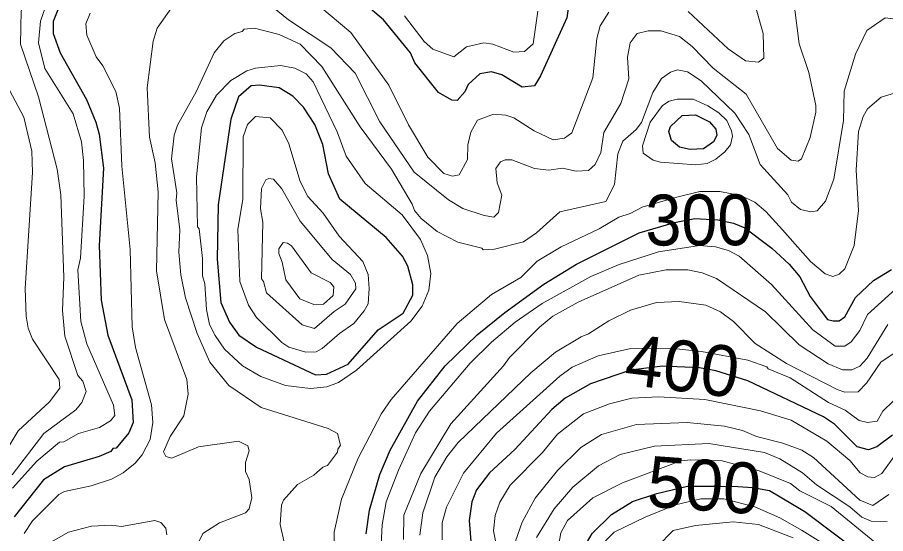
# Model space of a CAD drawing. Extents: x 673.3 to 698.5, y 6984.3 to 7012.3.
# Drawn here: x 677.359 to 678.725, y 6987.614 to 6988.426 of the extents above; entities that cross this region are included whole.
import ezdxf
from ezdxf.enums import TextEntityAlignment as Align

# ---------------------------------------------------------------- set-up
doc = ezdxf.new("R2010")
doc.units = 0
doc.header["$LTSCALE"] = 0.032
doc.layers.add('1', color=7, linetype='Continuous', lineweight=25)
doc.layers.add('2', color=7, linetype='Continuous', lineweight=13)
doc.layers.add('61', color=7, linetype='Continuous')

msp = doc.modelspace()

# ---------------------------------------------------------------- linework, layer by layer
at = {"layer": '1'}
for points in [[(678.2308, 6988.476), (678.2235, 6988.4254), (678.1819, 6988.3339), (678.1726, 6988.3184), (678.153, 6988.3161), (678.1211, 6988.3354), (678.1049, 6988.3403), (678.0865, 6988.337), (678.0683, 6988.3204), (678.063, 6988.3086), (678.0507, 6988.2949), (678.0422, 6988.2958), (678.0216, 6988.3079), (677.9844, 6988.3545), (677.9774, 6988.37), (677.9348, 6988.4223), (677.904, 6988.4481)], [(677.422, 6988.4378), (677.4151, 6988.4193), (677.4149, 6988.4004), (677.4261, 6988.3699), (677.4676, 6988.2967), (677.4823, 6988.2609), (677.4873, 6988.2424), (677.4939, 6988.1885), (677.4872, 6988.0671), (677.4905, 6987.9808)], [(677.9076, 6987.6132), (677.9126, 6987.6506), (677.9293, 6987.7065), (677.9453, 6987.745), (677.9885, 6987.8219), (678.0319, 6987.8776), (678.0824, 6987.9265), (678.1257, 6987.9617), (678.187, 6988.0061), (678.2387, 6988.0378), (678.3371, 6988.087), (678.3927, 6988.1033), (678.4249, 6988.1094), (678.4609, 6988.1073), (678.4857, 6988.1023), (678.5035, 6988.0947), (678.5459, 6988.0628), (678.5734, 6988.0377), (678.5901, 6988.0177), (678.6064, 6987.9868), (678.6222, 6987.9659), (678.6336, 6987.9507), (678.6425, 6987.9484), (678.6521, 6987.9482), (678.6608, 6987.9545), (678.678, 6987.9853), (678.7062, 6988.012), (678.7345, 6988.029)], [(677.4905, 6987.9808), (677.501, 6987.926), (677.5386, 6987.8241), (677.541, 6987.7886), (677.5342, 6987.772), (677.5143, 6987.7478), (677.5088, 6987.7475), (677.5056, 6987.7427), (677.4873, 6987.7349), (677.4326, 6987.7185), (677.3996, 6987.698), (677.3535, 6987.6398)], [(678.7361, 6987.7683), (678.7112, 6987.7501), (678.6981, 6987.7455), (678.6804, 6987.75), (678.6445, 6987.7858), (678.6272, 6987.7974), (678.5083, 6987.854), (678.4578, 6987.8696), (678.432, 6987.8742), (678.374, 6987.8773), (678.3238, 6987.8709), (678.2609, 6987.8493), (678.2208, 6987.8269), (678.1998, 6987.8087), (678.1418, 6987.7457), (678.1019, 6987.709), (678.081, 6987.6824), (678.0738, 6987.6635), (678.0696, 6987.634), (678.0725, 6987.6014)], [(678.2522, 6987.5947), (678.2632, 6987.6138), (678.2938, 6987.6435), (678.3269, 6987.664), (678.3652, 6987.6767), (678.4134, 6987.6883), (678.4624, 6987.6883), (678.4924, 6987.6877), (678.5161, 6987.6864), (678.5426, 6987.6814), (678.5979, 6987.6484), (678.7021, 6987.5702)]]:
    msp.add_lwpolyline(points, dxfattribs=at)
for points in [[(677.866, 6988.1401), (677.8485, 6988.1796), (677.8392, 6988.2261), (677.8268, 6988.2576), (677.8091, 6988.2848), (677.7921, 6988.3019), (677.7706, 6988.3152), (677.7399, 6988.3193), (677.7267, 6988.3182), (677.7064, 6988.3011), (677.6946, 6988.2659), (677.6747, 6988.131), (677.6729, 6988.0455), (677.6786, 6987.9775), (677.6925, 6987.9463), (677.7074, 6987.9257), (677.7351, 6987.907), (677.8278, 6987.8633), (677.8452, 6987.8644), (677.879, 6987.88), (677.9265, 6987.9342), (677.9659, 6987.9607), (677.9808, 6987.9889), (677.9808, 6988.0049), (677.9734, 6988.0342), (677.9647, 6988.0503), (677.939, 6988.0793)], [(678.4009, 6988.2216), (678.3884, 6988.2324), (678.3841, 6988.2466), (678.3866, 6988.2543), (678.4047, 6988.2713), (678.4259, 6988.2725), (678.448, 6988.2616), (678.458, 6988.2498), (678.4596, 6988.2399), (678.4544, 6988.2302), (678.4387, 6988.2193), (678.4176, 6988.2182)]]:
    msp.add_lwpolyline(points, close=True, dxfattribs=at)
at = {"layer": '2'}
for points in [[(678.5874, 6988.1997), (678.5927, 6988.2033), (678.6064, 6988.2367), (678.6151, 6988.2767), (678.6151, 6988.2872), (678.6044, 6988.3394), (678.5892, 6988.3842), (678.581, 6988.4461), (678.5809, 6988.4697), (678.5712, 6988.531), (678.5499, 6988.5749), (678.5402, 6988.6062), (678.5378, 6988.6342), (678.549, 6988.6536), (678.5587, 6988.6597), (678.5753, 6988.6612), (678.6114, 6988.6408), (678.6456, 6988.6286), (678.7055, 6988.5976), (678.7232, 6988.5929), (678.731, 6988.5991)], [(677.3506, 6987.7063), (677.4003, 6987.7712), (677.4506, 6987.8086), (677.46, 6987.82), (677.4668, 6987.8372), (677.4614, 6987.8537), (677.4535, 6987.8623), (677.4334, 6987.9244), (677.4294, 6987.9646), (677.4319, 6988.0173), (677.427, 6988.1468), (677.4214, 6988.1871), (677.392, 6988.3011), (677.3635, 6988.3836), (677.3643, 6988.4363), (677.3764, 6988.4594), (677.4061, 6988.4896), (677.4739, 6988.5301), (677.5594, 6988.5924)], [(678.5116, 6988.4751), (678.5322, 6988.4005), (678.5336, 6988.3617), (678.525, 6988.3552), (678.5048, 6988.3577), (678.4773, 6988.3764), (678.4146, 6988.435)], [(677.7348, 6988.4633), (677.7854, 6988.4222), (677.8519, 6988.378), (677.8903, 6988.3379), (677.929, 6988.2616), (677.9831, 6988.1826), (678.0369, 6988.139), (678.0597, 6988.1252), (678.0932, 6988.114), (678.1083, 6988.1116), (678.1161, 6988.1187), (678.1209, 6988.1462), (678.1137, 6988.1655), (678.1118, 6988.1882), (678.1189, 6988.1988), (678.1261, 6988.2019), (678.1368, 6988.2019), (678.1724, 6988.1879), (678.1951, 6988.1857), (678.2164, 6988.1889), (678.2382, 6988.1841), (678.2576, 6988.1849), (678.268, 6988.1945), (678.2768, 6988.2135), (678.2815, 6988.2449), (678.3083, 6988.2902), (678.3211, 6988.3291), (678.3187, 6988.3632), (678.3229, 6988.386), (678.3341, 6988.4004), (678.3515, 6988.4046), (678.3715, 6988.4048), (678.401, 6988.3957), (678.4208, 6988.38), (678.4539, 6988.3462), (678.5059, 6988.3053), (678.5551, 6988.2198), (678.5766, 6988.2012), (678.5874, 6988.1997)], [(677.3509, 6987.6853), (677.389, 6987.7274), (677.4249, 6987.7573), (677.4319, 6987.7582), (677.4547, 6987.7711), (677.4876, 6987.7803), (677.5052, 6987.7908), (677.5118, 6987.7994), (677.5101, 6987.8157), (677.4678, 6987.912), (677.4586, 6987.9472), (677.4538, 6988.0289), (677.4579, 6988.047), (677.4637, 6988.1445), (677.4628, 6988.2009), (677.4594, 6988.2303), (677.4464, 6988.2739), (677.4018, 6988.3453), (677.392, 6988.3858), (677.3952, 6988.4202), (677.4066, 6988.4528)], [(677.6383, 6987.5889), (677.6503, 6987.6139), (677.6768, 6987.6305), (677.7174, 6987.6464), (677.7234, 6987.6525), (677.7275, 6987.6697), (677.7234, 6987.6987), (677.7178, 6987.7112), (677.7178, 6987.7253), (677.7233, 6987.744), (677.7214, 6987.7518), (677.7068, 6987.7589), (677.6439, 6987.75), (677.6016, 6987.7321), (677.592, 6987.7351), (677.5884, 6987.7424), (677.5993, 6987.7666), (677.6205, 6987.7991), (677.6273, 6987.8328), (677.6254, 6987.856), (677.59, 6987.9505), (677.5777, 6988.0271), (677.5801, 6988.1515), (677.5752, 6988.1971), (677.5663, 6988.2376), (677.5631, 6988.3149), (677.5725, 6988.3883), (677.5785, 6988.4088), (677.601, 6988.4412)], [(678.03, 6988.18), (678.0045, 6988.2058), (677.9744, 6988.2571), (677.9432, 6988.3195), (677.8832, 6988.4021), (677.8345, 6988.4429)], [(677.9677, 6988.4283), (677.9989, 6988.3882), (678.0127, 6988.3758), (678.0457, 6988.3641), (678.0657, 6988.3795), (678.0929, 6988.386), (678.1068, 6988.3836), (678.1402, 6988.3714), (678.1566, 6988.3722), (678.1703, 6988.3841), (678.1776, 6988.4356)], [(678.2894, 6988.4339), (678.2759, 6988.4127), (678.2708, 6988.3928), (678.2642, 6988.3309), (678.2313, 6988.2442), (678.2196, 6988.2359), (678.2019, 6988.233), (678.1719, 6988.2472), (678.1399, 6988.2678), (678.1272, 6988.2721), (678.1078, 6988.2736), (678.0827, 6988.2643), (678.0723, 6988.2452), (678.0678, 6988.2254), (678.0671, 6988.2023), (678.0538, 6988.1784), (678.0434, 6988.176), (678.03, 6988.18)], [(677.4731, 6988.4326), (677.4663, 6988.4159), (677.4679, 6988.3981), (677.4827, 6988.364), (677.4932, 6988.3497), (677.5138, 6988.3093), (677.5191, 6988.2829), (677.5231, 6988.192), (677.5361, 6988.0609), (677.5395, 6987.9389), (677.5444, 6987.9067), (677.5695, 6987.8162), (677.5719, 6987.7883), (677.5676, 6987.7617), (677.5548, 6987.7373), (677.5439, 6987.7244), (677.5253, 6987.7091), (677.5066, 6987.6993), (677.4745, 6987.689), (677.4326, 6987.6801), (677.4238, 6987.675), (677.3824, 6987.6335), (677.3693, 6987.6135)], [(678.7446, 6988.4226), (678.7246, 6988.4251), (678.6958, 6988.4052), (678.6777, 6988.3682), (678.66, 6988.3098), (678.6591, 6988.2637), (678.6438, 6988.1716), (678.6306, 6988.1369), (678.6173, 6988.1213), (678.6076, 6988.1199), (678.5913, 6988.1238), (678.5771, 6988.1351), (678.571, 6988.1467), (678.5277, 6988.1944), (678.51, 6988.2414), (678.4881, 6988.2753), (678.435, 6988.3259), (678.4132, 6988.3403), (678.3978, 6988.3435), (678.3864, 6988.3396), (678.3722, 6988.33), (678.3586, 6988.3078), (678.3407, 6988.2607), (678.3328, 6988.2495), (678.3113, 6988.231), (678.3037, 6988.2113), (678.2982, 6988.1628), (678.2846, 6988.1363)], [(678.2846, 6988.1363), (678.2126, 6988.1199), (678.1757, 6988.0867), (678.1552, 6988.0726), (678.1097, 6988.0611), (678.0918, 6988.0603), (678.0897, 6988.0627), (678.0519, 6988.0721), (678.0191, 6988.0889), (677.9939, 6988.1092), (677.9834, 6988.122), (677.9798, 6988.132), (677.9476, 6988.1871), (677.8979, 6988.2539), (677.8376, 6988.3484), (677.8038, 6988.3838), (677.7704, 6988.3988), (677.7319, 6988.4088), (677.7156, 6988.4072), (677.7123, 6988.4039), (677.7007, 6988.4007), (677.6835, 6988.3891), (677.6685, 6988.3699), (677.64, 6988.3089), (677.6104, 6988.2562), (677.6053, 6988.2408), (677.6014, 6988.2031), (677.6094, 6988.1498), (677.6087, 6988.1382), (677.6143, 6988.0915), (677.6127, 6988.0564), (677.616, 6988.021), (677.6231, 6987.9844), (677.6418, 6987.9286), (677.6613, 6987.8834), (677.6914, 6987.8464), (677.7424, 6987.8121), (677.8478, 6987.779), (677.8626, 6987.771), (677.8674, 6987.7526), (677.8629, 6987.7467), (677.8626, 6987.742), (677.8465, 6987.7208), (677.8392, 6987.7182), (677.825, 6987.7055), (677.7995, 6987.6909), (677.7773, 6987.666), (677.7743, 6987.6583), (677.7723, 6987.6278), (677.7788, 6987.5977)], [(677.3337, 6987.7318), (677.3596, 6987.7754), (677.4091, 6987.8208), (677.4252, 6987.8422), (677.4243, 6987.8559), (677.3825, 6987.9197), (677.3755, 6987.9371), (677.3724, 6987.956), (677.3709, 6987.9994), (677.3822, 6988.1818), (677.3813, 6988.2153), (677.3689, 6988.269), (677.3462, 6988.3114)], [(678.6899, 6988.2698), (678.6966, 6988.2818), (678.7184, 6988.3003), (678.739, 6988.3069)], [(677.857, 6987.5827), (677.857, 6987.6159), (677.8685, 6987.668), (677.8951, 6987.7322), (677.9315, 6987.8026), (677.9467, 6987.8244), (678.0506, 6987.9444), (678.1049, 6987.9896), (678.1509, 6988.0164), (678.1768, 6988.0421), (678.2143, 6988.065), (678.2743, 6988.093), (678.305, 6988.1115), (678.3231, 6988.1174), (678.3422, 6988.1273), (678.3967, 6988.1432), (678.4326, 6988.1518), (678.4644, 6988.1518), (678.4968, 6988.1456), (678.5191, 6988.135), (678.5366, 6988.1207), (678.5631, 6988.0917), (678.6068, 6988.0417), (678.6301, 6988.0223), (678.6421, 6988.018), (678.6518, 6988.022), (678.661, 6988.0305), (678.6755, 6988.0671), (678.6827, 6988.122), (678.6787, 6988.1857), (678.6825, 6988.2466), (678.6899, 6988.2698)], [(678.7627, 6988.0182), (678.6968, 6987.9586), (678.6844, 6987.9333), (678.6712, 6987.9155), (678.661, 6987.9087), (678.6456, 6987.9087), (678.6108, 6987.9343), (678.5454, 6988.0054), (678.4949, 6988.05), (678.4778, 6988.0593), (678.4573, 6988.065), (678.4322, 6988.0667), (678.3675, 6988.0572), (678.3059, 6988.0372), (678.2612, 6988.0181), (678.1845, 6987.9755), (678.142, 6987.9462), (678.1049, 6987.9147), (678.0713, 6987.8819), (678.007, 6987.8063), (677.985, 6987.7723), (677.9582, 6987.7134), (677.9391, 6987.6638), (677.9326, 6987.6276), (677.9313, 6987.5966)], [(677.9662, 6987.6043), (677.9669, 6987.6427), (677.9937, 6987.7082), (678.0406, 6987.7861), (678.1239, 6987.8776), (678.1331, 6987.8909), (678.1804, 6987.9383), (678.2013, 6987.9556), (678.2411, 6987.9779), (678.3369, 6988.0201), (678.3796, 6988.0285), (678.414, 6988.0285), (678.4366, 6988.0237), (678.459, 6988.0149), (678.536, 6987.9627), (678.5889, 6987.9108), (678.6349, 6987.8806), (678.6571, 6987.8714), (678.6721, 6987.8714), (678.6846, 6987.8772), (678.6962, 6987.8895), (678.7288, 6987.9425)], [(678.7549, 6987.9085), (678.7176, 6987.8833), (678.6953, 6987.8501), (678.6821, 6987.8365), (678.6611, 6987.8362), (678.6491, 6987.8402), (678.569, 6987.8815), (678.5198, 6987.913), (678.486, 6987.9475), (678.4651, 6987.9627), (678.4422, 6987.9732), (678.4, 6987.9788), (678.3646, 6987.9771), (678.3234, 6987.9652), (678.2896, 6987.9484), (678.2577, 6987.9277), (678.2461, 6987.9233), (678.2055, 6987.899), (678.1667, 6987.8665), (678.0526, 6987.7567), (678.0344, 6987.7343), (678.0159, 6987.7022), (677.997, 6987.6464), (677.9922, 6987.611)], [(678.0273, 6987.6039), (678.0273, 6987.6303), (678.0342, 6987.6552), (678.0607, 6987.7087), (678.1126, 6987.7719), (678.2126, 6987.8612), (678.2316, 6987.8753), (678.2726, 6987.8934), (678.3241, 6987.9047), (678.3859, 6987.9055), (678.4352, 6987.9004), (678.5084, 6987.8867), (678.5384, 6987.8762), (678.5405, 6987.873), (678.5751, 6987.8585), (678.6355, 6987.8197), (678.6616, 6987.8078), (678.6838, 6987.7917), (678.6965, 6987.7883), (678.7118, 6987.7907), (678.7206, 6987.8065), (678.7368, 6987.8218)], [(678.6853, 6987.7093), (678.669, 6987.7288), (678.6328, 6987.7593), (678.5764, 6987.7922), (678.5283, 6987.8069), (678.4406, 6987.8246), (678.3678, 6987.8286), (678.3257, 6987.8265), (678.2907, 6987.8179), (678.2496, 6987.8021), (678.2088, 6987.7703), (678.1853, 6987.7413), (678.1344, 6987.6896), (678.1179, 6987.6633), (678.1104, 6987.6423), (678.1079, 6987.6182), (678.1148, 6987.5831)], [(678.1426, 6987.6016), (678.1533, 6987.6317), (678.1736, 6987.6692), (678.2086, 6987.7131), (678.2454, 6987.7491), (678.2782, 6987.7694), (678.3329, 6987.7851), (678.4129, 6987.7883), (678.4716, 6987.7824), (678.5, 6987.7761), (678.5218, 6987.7666), (678.5633, 6987.7559), (678.5935, 6987.745), (678.6117, 6987.7331)], [(678.5344, 6987.7411), (678.4469, 6987.7556), (678.3614, 6987.751), (678.3071, 6987.7381), (678.2734, 6987.7203), (678.2328, 6987.6867), (678.2033, 6987.6525), (678.1757, 6987.6074)], [(678.7278, 6987.6327), (678.7025, 6987.6331), (678.6875, 6987.6392), (678.6687, 6987.6556), (678.6166, 6987.6905), (678.5946, 6987.7094), (678.5586, 6987.7313), (678.5344, 6987.7411)], [(678.7421, 6987.74), (678.7193, 6987.7083), (678.7075, 6987.702), (678.6973, 6987.7028), (678.6853, 6987.7093)], [(678.2088, 6987.585), (678.2139, 6987.6146), (678.2246, 6987.6344), (678.2644, 6987.6698), (678.3108, 6987.6936), (678.4026, 6987.728), (678.4186, 6987.7297), (678.4681, 6987.728), (678.5259, 6987.7126), (678.5756, 6987.6924), (678.5903, 6987.6811), (678.6396, 6987.6563), (678.7083, 6987.6)], [(678.6117, 6987.7331), (678.6847, 6987.666), (678.7053, 6987.658), (678.73, 6987.6751)], [(678.6402, 6987.5896), (678.5936, 6987.6183), (678.5587, 6987.6386), (678.5191, 6987.6557), (678.4707, 6987.6684), (678.4345, 6987.6684), (678.3943, 6987.659), (678.3468, 6987.6392), (678.298, 6987.6161), (678.2841, 6987.6024)], [(677.4077, 6987.5978), (677.4389, 6987.6158), (677.4754, 6987.6253), (677.5067, 6987.6271), (677.5224, 6987.6247), (677.5747, 6987.6343), (677.5842, 6987.6311), (677.5924, 6987.6219), (677.5938, 6987.6114)], [(678.3661, 6987.5931), (678.391, 6987.6186), (678.4257, 6987.6263), (678.4852, 6987.632), (678.5251, 6987.6278), (678.5797, 6987.6069)]]:
    msp.add_lwpolyline(points, dxfattribs=at)
for points in [[(678.0092, 6988.0231), (678.0042, 6988.0512), (677.993, 6988.0765), (677.9643, 6988.115), (677.906, 6988.1643), (677.8762, 6988.2074), (677.8618, 6988.2459), (677.8242, 6988.3244), (677.813, 6988.3371), (677.7951, 6988.3461), (677.7725, 6988.3501), (677.7332, 6988.3461), (677.7196, 6988.3417), (677.6944, 6988.3267), (677.672, 6988.3035), (677.6569, 6988.2775), (677.6485, 6988.2519), (677.6404, 6988.175), (677.642, 6988.0965), (677.6445, 6988.093), (677.6501, 6988.0463), (677.6502, 6988.0193), (677.6534, 6988.0065), (677.656, 6987.9662), (677.6612, 6987.9426), (677.6697, 6987.9255), (677.6847, 6987.904), (677.713, 6987.8775), (677.7416, 6987.8606), (677.7807, 6987.8469), (677.8202, 6987.8421), (677.8456, 6987.8445), (677.8642, 6987.8513), (677.8923, 6987.8709), (677.978, 6987.9477), (677.9955, 6987.9713), (678.006, 6987.9967)], [(678.472, 6988.2143), (678.4808, 6988.2256), (678.484, 6988.2389), (678.4828, 6988.2472), (678.4751, 6988.2639), (678.4624, 6988.2758), (678.4456, 6988.2868), (678.4222, 6988.2972), (678.3972, 6988.2971), (678.3847, 6988.2939), (678.3742, 6988.2874), (678.3547, 6988.2608), (678.3424, 6988.224), (678.3437, 6988.2121), (678.3594, 6988.2015), (678.3709, 6988.1979), (678.4264, 6988.1939), (678.4442, 6988.1961), (678.4578, 6988.2026)], [(677.9044, 6987.964), (677.9106, 6987.9754), (677.9123, 6987.9995), (677.9107, 6988.0212), (677.9021, 6988.0418), (677.8649, 6988.0814), (677.8401, 6988.1179), (677.8156, 6988.1443), (677.8039, 6988.1675), (677.7857, 6988.227), (677.7751, 6988.2482), (677.7562, 6988.2678), (677.7336, 6988.2701), (677.721, 6988.2573), (677.7141, 6988.2378), (677.7136, 6988.1401), (677.7055, 6988.0922), (677.7088, 6988.0104), (677.7223, 6987.9729), (677.7347, 6987.9537), (677.7749, 6987.9141), (677.7857, 6987.907), (677.8124, 6987.8991), (677.829, 6987.8998), (677.8385, 6987.9049), (677.8656, 6987.9287), (677.8881, 6987.944)], [(677.8911, 6987.9987), (677.891, 6988.0075), (677.883, 6988.0212), (677.8542, 6988.0451), (677.8035, 6988.1052), (677.7749, 6988.1562), (677.7619, 6988.1716), (677.7541, 6988.1725), (677.7496, 6988.1702), (677.7428, 6988.1569), (677.7414, 6988.1248), (677.7447, 6988.1036), (677.7429, 6988.0147), (677.7462, 6988.0104), (677.7508, 6987.9923), (677.8066, 6987.9423), (677.826, 6987.9365), (677.857, 6987.9633), (677.8745, 6987.9744)], [(677.851, 6988.0087), (677.8209, 6988.024), (677.7902, 6988.0666), (677.7835, 6988.0708), (677.7767, 6988.0715), (677.7699, 6988.0616), (677.7699, 6988.0546), (677.7755, 6988.0407), (677.7811, 6988.0127), (677.8032, 6987.983), (677.8251, 6987.974), (677.8406, 6987.9749), (677.8554, 6987.9885), (677.8568, 6988.0021)]]:
    msp.add_lwpolyline(points, close=True, dxfattribs=at)

# ---------------------------------------------------------------- texts
at = {"layer": '61', "width": 0.95}
msp.add_text('300', height=0.08, rotation=0.207, dxfattribs=at).set_placement((678.4321, 6988.0672), align=Align.CENTER)
at = {"layer": '61'}
for s, rotation, p in [('400', 352.985, (678.4005, 6987.8378)), ('500', 355.914, (678.4369, 6987.65))]:
    msp.add_text(s, height=0.08, rotation=rotation, dxfattribs=at).set_placement(p, align=Align.CENTER)

doc.saveas('drawing.dxf')
